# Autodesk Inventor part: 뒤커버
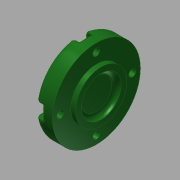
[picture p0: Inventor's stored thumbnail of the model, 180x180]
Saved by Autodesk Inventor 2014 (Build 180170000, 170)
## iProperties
Created: 2015-11
Part Number: 뒤커버
Material: 알루미늄 6061
Document SubType Name: Modeling
Designer: mduedu
Density: 1 g/cm^3
Appearance: 매끄러움 - 짙은 산림 녹색
Author: mduedu
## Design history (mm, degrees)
sketch "스케치1"
  geometry: L1 (-7, 0)-(7, 0); L2 (-7, 0)-(-7, 27.5); L3 (-7, 27.5)-(4, 27.5); L4 (4, 27.5)-(4, 16); L5 (4, 16)-(7, 16); L6 (7, 16)-(7, 0); 2 further points
  constraints: 12 end point, 3 perpendicular, 2 parallel, 1 coincident, 1 horizontal, 1 midpoint
  dimensions: "d0" = 14 distance of L1.start L1.end; "d1" = 55 diameter of L3 L1; "d2" = 3 distance of L4.end L5.end; "d3" = 32 diameter of L5 L1
revolve "회전1" sketch "스케치1" stored, may be unused: angle "d4" = 90 deg
hole "구멍1" diameter "d7" = 25; stored, may be unused: countersink angle "d11" = 90 deg, drill point angle "d13" = 0 deg; dims "d5" = 10, "d6" = 10, "d8" = 6, "d9" = 4, "d10" = 2, "d12" = 3
fillet "모깎기2" dims "d36" = 3
fillet "모깎기3" dims "d37" = 3
sketch "스케치2" dims "d39" = 45
  geometry: C1 r 12.846 at (0, 0) reference; C2 r 24.5 at (0, 0) reference; 6 further points
  constraints: 2 vertical alignment, 1 coincident, 7 other
  dimensions: "d42" = 360 deg dimension on point (0, 0) point (0, 22.5) (derived)
sketch "스케치3"
  geometry: 8 further points
  constraints: 4 coincident
hole "구멍4" sketch "스케치3" at (-22.5, 0), (0, -22.5), (22.5, 0), (0, 22.5) diameter "d44" = 4.5; stored, may be unused: countersink angle "d48" = 90 deg, drill point angle "d50" = 0 deg; dims "d45" = 6, "d46" = 8, "d47" = 4.6, "d49" = 8
sketch "스케치4"
  geometry: L1 (-4, 0)-(-4, -4.708); L2 (4, 0)-(4, -4.708); A1 r 4 centre (0, 0) between (-4, 0) and (4, 0) reference; A2 r 27.5 centre (0, 22.5) between (-4, -4.708) and (4, -4.708) reference; 3 further points
  constraints: 4 end point, 4 point on circle, 2 tangent, 1 parallel, 1 vertical
extrude "돌출1" cut sketch "스케치4" stored distance "d51" = 0; taper "d52" = 0 deg
fillet "모깎기5" dims "d56" = 0.3
fillet "모깎기6" dims "d57" = 1
node "솔리드1"
pattern_circular "원형 패턴1" dims angle "d54" = 360 deg
